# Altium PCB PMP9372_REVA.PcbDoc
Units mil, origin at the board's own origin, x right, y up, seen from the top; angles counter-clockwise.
Board outline 4200 x 2100 mil, 6 copper layers (Top Layer, InternalPlane1, MidLayer2, MidLayer3, InternalPlane2, Bottom Layer), stack 63 mil thick; 93 components, 37 nets, 190 pads, 51 vias.
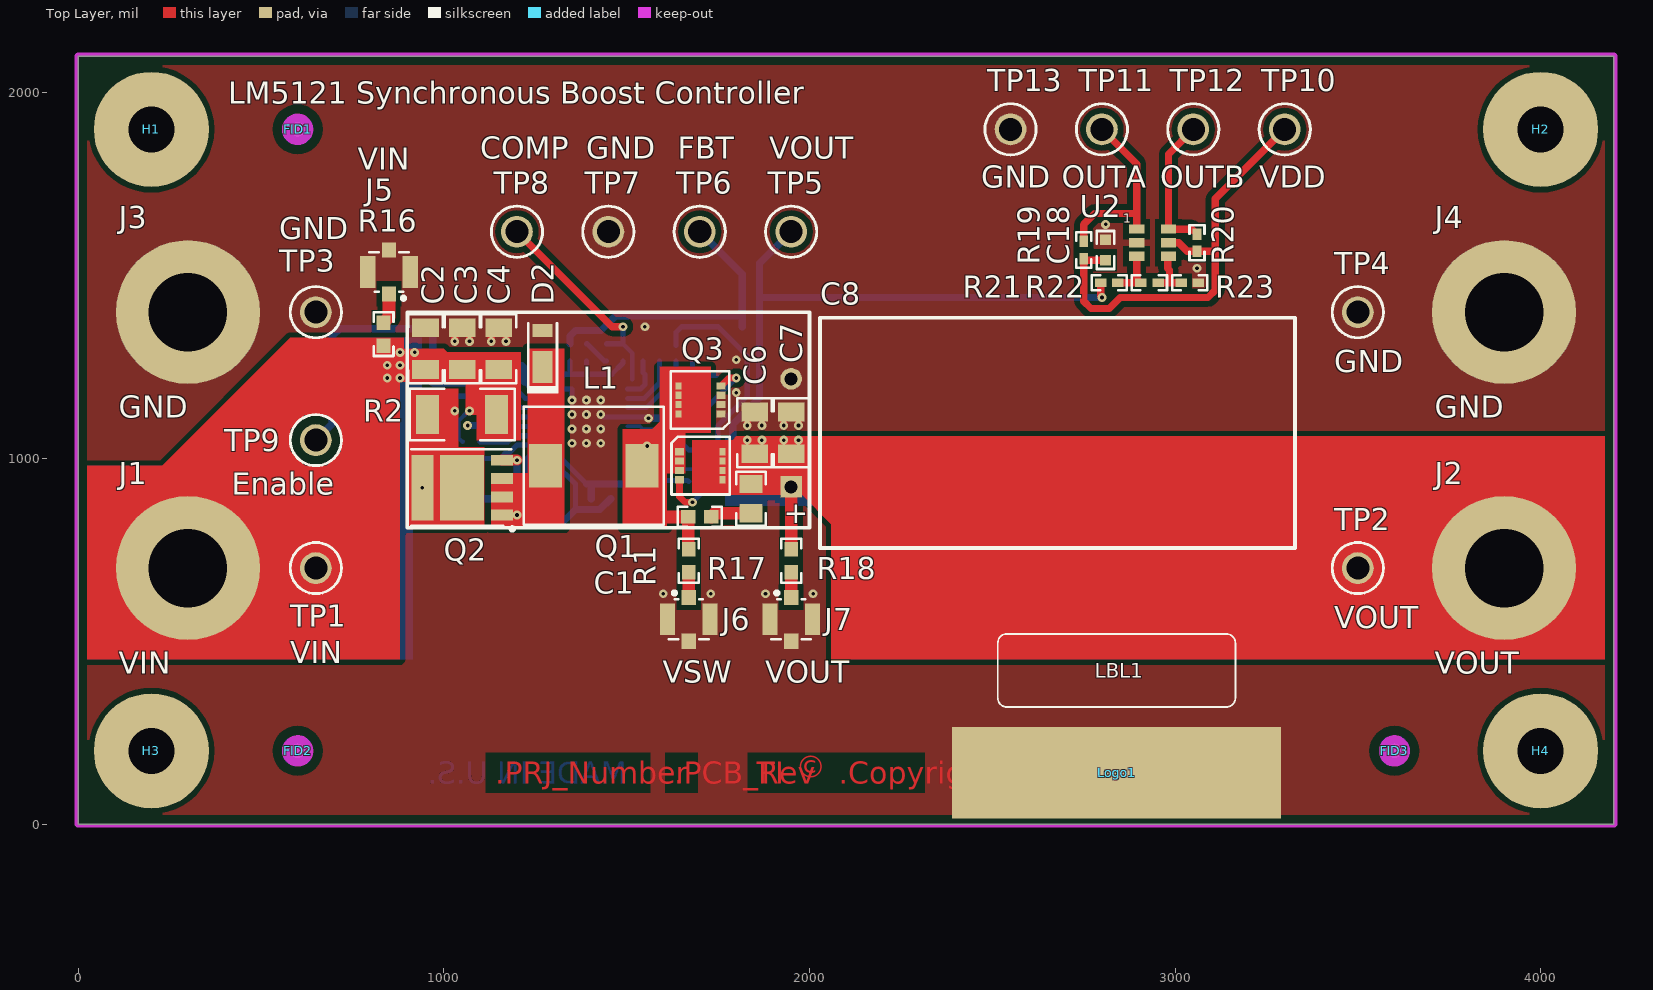
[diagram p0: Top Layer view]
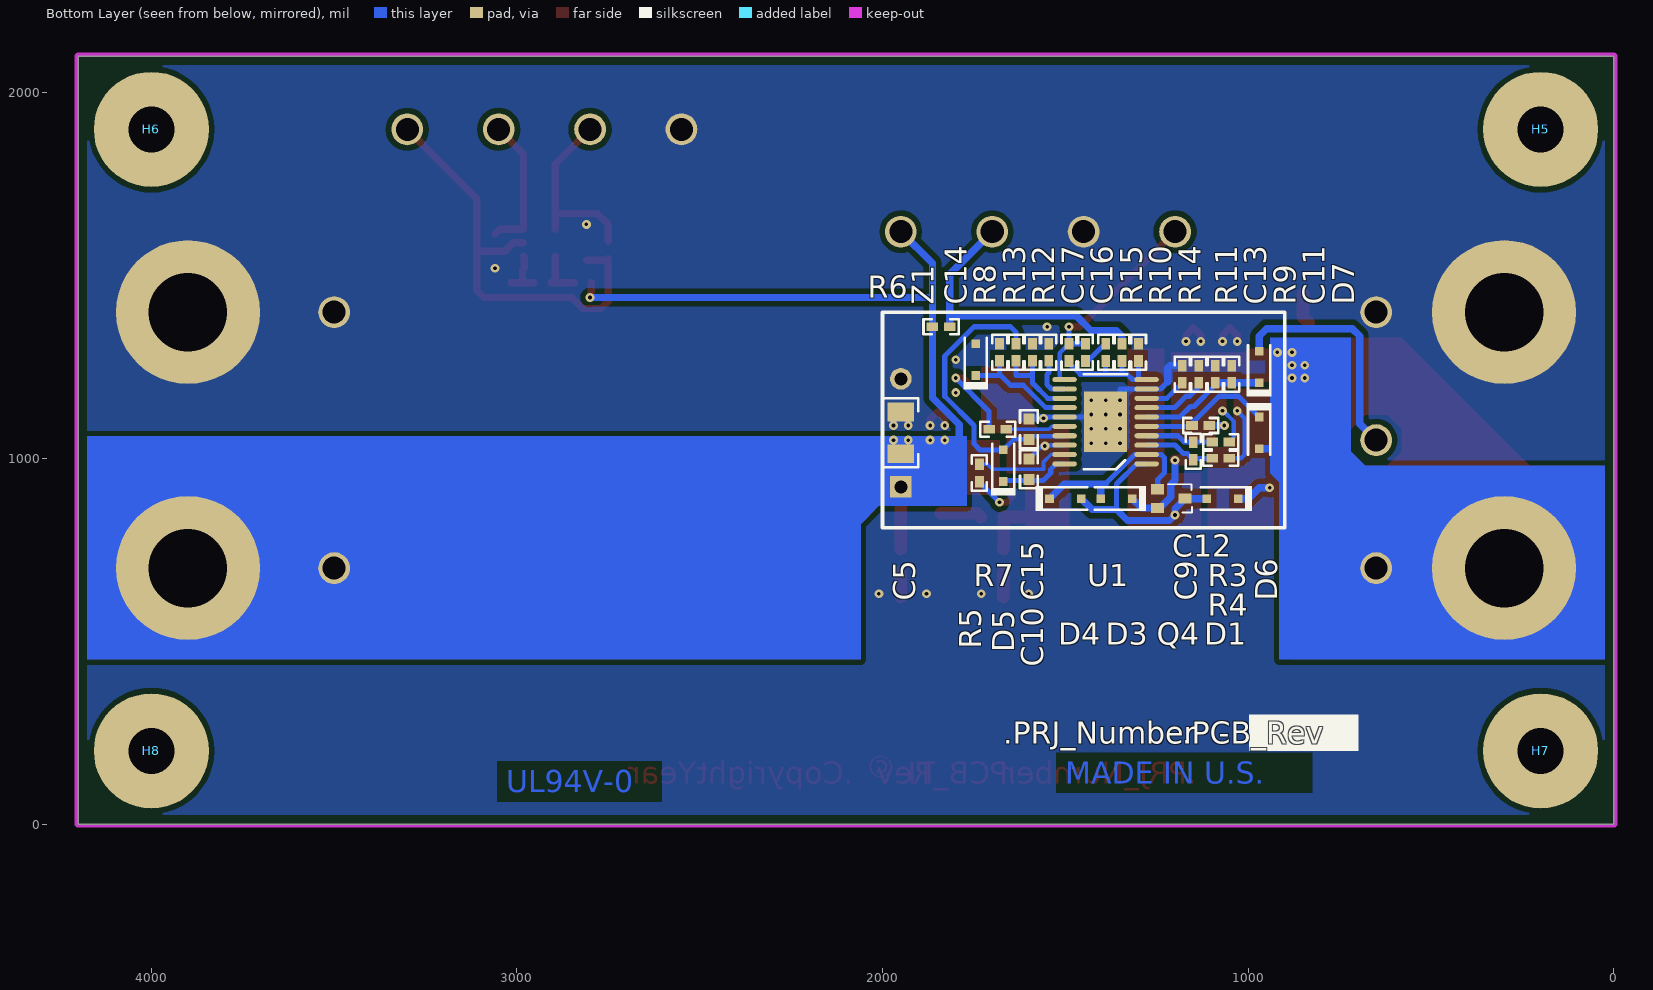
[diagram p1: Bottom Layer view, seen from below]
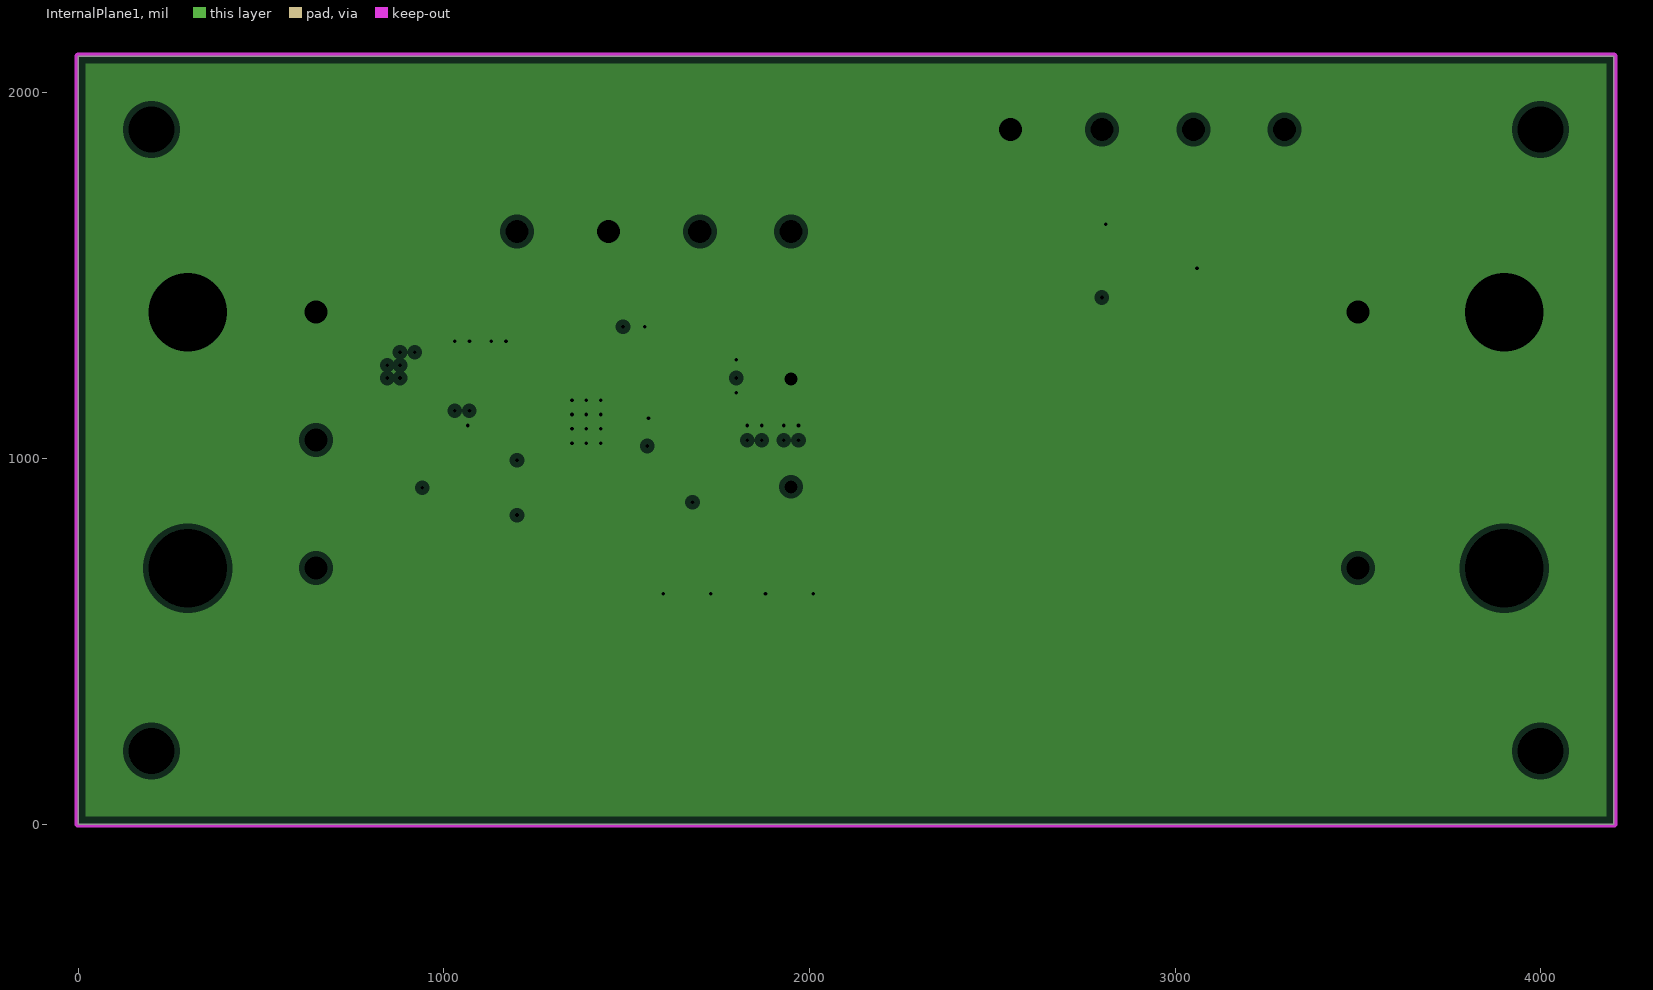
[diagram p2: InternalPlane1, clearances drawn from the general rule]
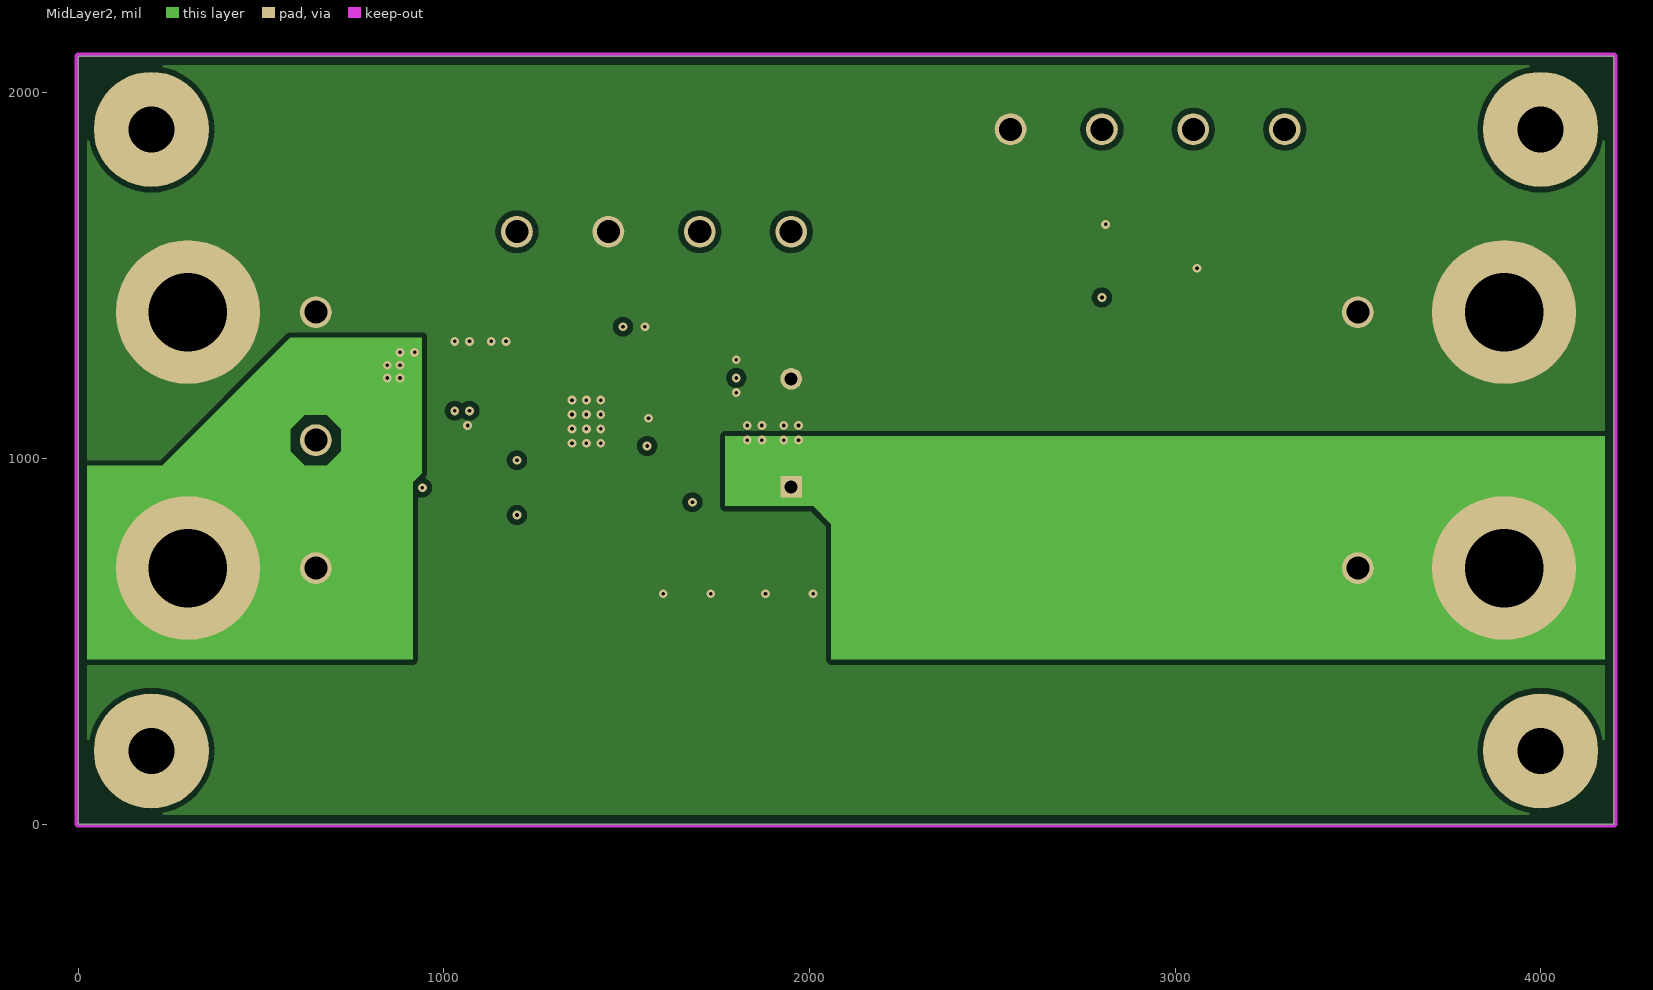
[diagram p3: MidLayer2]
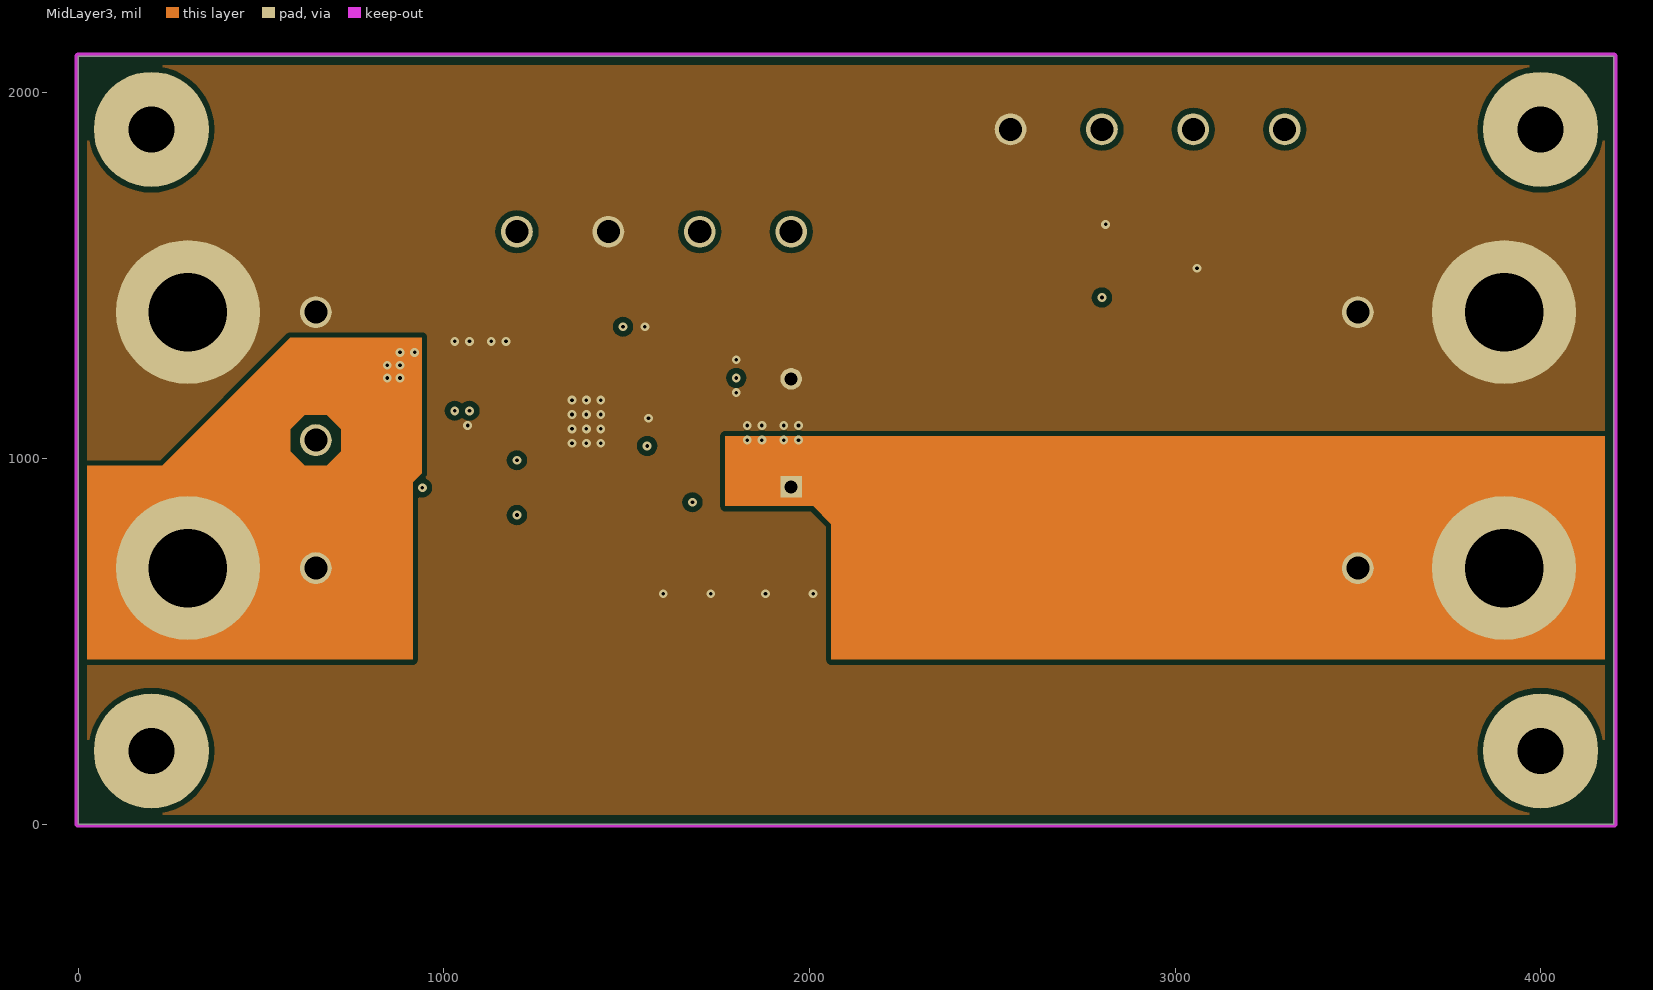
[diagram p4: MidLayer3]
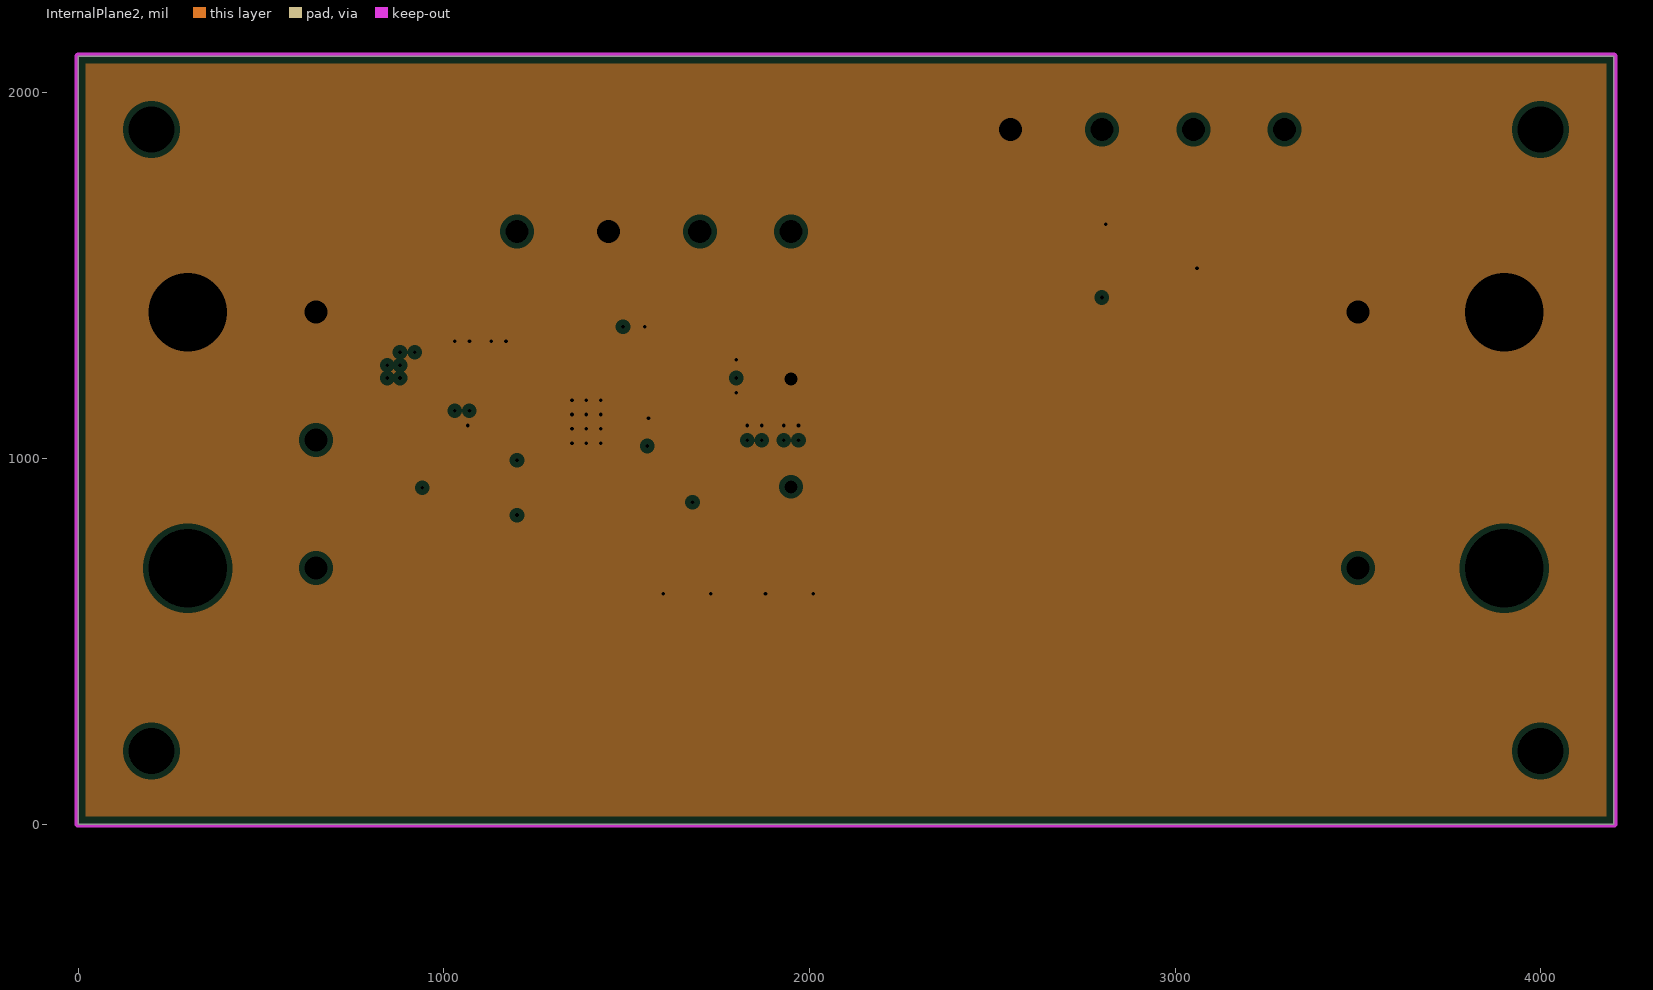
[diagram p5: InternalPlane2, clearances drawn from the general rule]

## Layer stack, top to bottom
Top Layer: signal copper 0.7
Dielectric: core 11.5, FR-4, Dk 4.8
InternalPlane1: plane copper 1.4, net GND
Dielectric: prepreg 11.5, FR-4, Dk 4.8
MidLayer2: signal copper 0.7
Dielectric: core 11.4, FR-4, Dk 4.8
MidLayer3: signal copper 0.7
Dielectric: prepreg 11.5, FR-4, Dk 4.8
InternalPlane2: plane copper 1.4, net GND
Dielectric: core 11.5, FR-4, Dk 4.8
Bottom Layer: signal copper 0.7

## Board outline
0,0 4200,0 4200,2100 0,2100

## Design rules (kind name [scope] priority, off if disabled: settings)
AcuteAngle [All] p1: minimum=4.50000000000000E+0001 checktracksonly=FALSE
AssemblyTestPointUsage [All] p1: valid=2
Clearance Clearance_TRANS_NexFET_Q3 [HasFootprint('TRANS_NexFET_Q3') vs HasFootprint('TRANS_NexFET_Q3')] p1: gap=5.9
Clearance Clearance_BoardEdge_MountingHoles [OnCopper and InComponentClass('Mounting Holes') vs IsKeepOut] p2: gap=40
Clearance Clearance_BoardEdge_Poly [OnCopper and (InPoly or IsCopperRegion or IsTrack or IsFill) vs IsKeepOut] p3: gap=25
Clearance Clearance_BoardEdge [OnCopper and Not InComponentClass('Logo') and not InComponentClass('FiducialMark') and not InRegion(1000,500,4000,800) and Not IsKeepout vs IsKeepOut] p4: gap=75
Clearance Clearance_Poly [InPolygon] p5: gap=15
Clearance [All] p6: gap=8
ComponentClearance ComponentClearance_CAPPR [HasFootprint('CAPPR7.5-16X31.5H*') vs HasFootprint('1206') OR HasFootprint('0805*') OR HasFootprint('0603*')OR HasFootprint('0402*')] p1: gap=0 collisioncheckmode=3 verticalgap=0 showdistances=FALSE
ComponentClearance ComponentClearance_Shunt [InComponentClass('Header') vs InComponentClass('Shunt')] p2: gap=0 collisioncheckmode=3 verticalgap=0 showdistances=FALSE
ComponentClearance ComponentClearance_Logo [InComponentClass('Logo')] p3: gap=50 collisioncheckmode=3 verticalgap=10 showdistances=FALSE
ComponentClearance ComponentClearance_ScrewToNut [(HasFootprint('NY PMS 440 0025 PH')) vs (HasFootprint('Keystone_1902C'))] p4: gap=5 collisioncheckmode=3 verticalgap=10 showdistances=FALSE
ComponentClearance ComponentClearance_MountingHoles [InComponentClass('Mounting Holes')] p5: gap=200 collisioncheckmode=3 verticalgap=100000 showdistances=FALSE
ComponentClearance ComponentClearance_SmallSMT [HasFootprint('0201*') or HasFootprint('0402*') or HasFootprint('0508') or HasFootprint('0603*') or HasFootprint('0612') or HasFootprint('0805*') or HasFootprint('0815*') or HasFootprint('0830*') or HasFootprint('1206*') or HasFootprint('1210*') or HasFootprint('1808*') or HasFootprint('1812*') or HasFootprint('1825*') or HasFootprint('2010*') or HasFootprint('2220*') or HasFootprint('2225*') or HasFootprint('2512*') or HasFootprint('2728*') or HasFootprint('3518*') or HasFootprint('sod-323*') or HasFootprint('sot-323*')or HasFootprint('sot23-6') vs HasFootprint('0201*') or HasFootprint('0402*') or HasFootprint('0508') or HasFootprint('0603*') or HasFootprint('0612') or HasFootprint('0805*') or HasFootprint('0815*') or HasFootprint('0830*') or HasFootprint('1206*') or HasFootprint('1210*') or HasFootprint('1808*') or HasFootprint('1812*') or HasFootprint('1825*') or HasFootprint('2010*') or HasFootprint('2220*') or HasFootprint('2225*') or HasFootprint('2512*') or HasFootprint('2728*') or HasFootprint('3518*') or HasFootprint('sod-323*') or HasFootprint('sot-323*') or HasFootprint('sot23-6')] p6: gap=20 collisioncheckmode=3 verticalgap=10 showdistances=FALSE
ComponentClearance ComponentClearance_THtoSMT [IsThruComponent vs IsSMTComponent] p7: gap=100 collisioncheckmode=3 verticalgap=30 showdistances=FALSE
ComponentClearance ComponentClearance_THtoTH [IsThruComponent vs IsThruComponent] p8: gap=100 collisioncheckmode=3 verticalgap=30 showdistances=FALSE
ComponentClearance [All] p9: gap=40 collisioncheckmode=3 verticalgap=10 showdistances=FALSE
DiffPairsRouting [All] p1: maxlimit=100 minlimit=10 mostfreqgap=10 maxuncoupledlength=1000
FabricationTestPointUsage TestPointUsage [All] p1: valid=2 allowmultiple=FALSE
FabricationTestpoint Testpoint [All] p1: side=3 testpointundercomponent=TRUE minsize=40 maxsize=100 preferedsize=60 minholesize=0 maxholesize=40 preferedholesize=32 testpointgrid=1 allowsidetop=TRUE allowsidebottom=TRUE usegrid=TRUE gridtolerance=0.01
FanoutControl Fanout_LCC [IsLCC] p1: bgadir=Out bgaviamode=Centered fanoutstyle=Auto fanoutdirection=Alternating viagrid=1 // Fanout_LCC (Default Rule)
FanoutControl Fanout_BGA [IsBGA] p2: bgadir=Out bgaviamode=Centered fanoutstyle=Auto fanoutdirection=Alternating viagrid=1 // Fanout_BGA (Default Rule)
FanoutControl Fanout_Default [All] p4: bgadir=Out bgaviamode=Centered fanoutstyle=Auto fanoutdirection=Alternating viagrid=1 // Fanout_Default (Default Rule)
FanoutControl Fanout_Small [(CompPinCount < 5)] p5: bgadir=Out bgaviamode=Centered fanoutstyle=Auto fanoutdirection=OutThenIn viagrid=1 // Fanout_Small (Default Rule)
HoleSize [All] p1: absolutevalues=TRUE maxlimit=251 minlimit=8 maxpercent=80.000 minpercent=20.000
MinimumAnnularRing MinimumAnnularRing_ThermalPadVias [IsVia and InAnyComponent] p1: minimumring=5.91
MinimumAnnularRing [All] p2: minimumring=6
MinimumSolderMaskSliver MinimumSolderMaskSliver_Logo [InComponentClass('Logo') vs InComponentClass('Logo')] p1: minsoldermaskwidth=0.7
MinimumSolderMaskSliver [All] p2: minsoldermaskwidth=3.94
PlaneClearance [All] p1: clearance=15
PlaneConnect [All] p1: planeconnectstyle=Direct reliefexpansion=10 reliefentries=4 reliefconductorwidth=10 reliefairgap=10
PolygonConnect [All] p1: connectstyle=Direct reliefconductorwidth=10 reliefentries=4 polygonreliefangle="90 Angle" airgapwidth=10
RoutingVias ThermalPadVias [IsVia and InAnyComponent] p1: holewidth=10 width=24 viastyle="Through Hole" minholewidth=10 minwidth=24 maxholewidth=10 maxwidth=24
RoutingVias [All] p2: holewidth=16 width=34 viastyle="Through Hole" minholewidth=10 minwidth=24 maxholewidth=40 maxwidth=65
SMDToCorner [All] p1: distance=30000
SilkToSilkClearance [All] p1: silktosilkclearance=5
SilkscreenOverComponentPads [All] p1: minsilkscreentomaskgap=5
SolderMaskExpansion [All] p1: expansion=1.97
Width [All] p1: maxlimit=100 minlimit=10 preferedwidth=10 checkconnectedcopper=TRUE
13 further rules are at their usual default settings.

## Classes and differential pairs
component class "Mounting Holes": H1 H2 H3 H4
component class Logo: Logo1
component class PMP9372_REVA_Sh2: FID1 FID2 FID3 H1 H2 H3 H4 H5 H6 H7 H8 LBL1 Logo1 ZZ1 ZZ2 ZZ3 ZZ4
component class FiducialMark: FID1 FID2 FID3
component class AssemblyNote: ZZ1 ZZ2 ZZ3 ZZ4
component class Label: LBL1

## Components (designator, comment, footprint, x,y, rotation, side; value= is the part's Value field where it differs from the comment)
C1 "GRM1885C1H681JA01D" 0603 1700,840 r180 top
C2 "GRM31CR61E226KE15L" 1206 950,1300 r90 top
C3 "GRM31CR61E226KE15L" 1206 1050,1300 r90 top
C4 "GRM31CR61E226KE15L" 1206 1150,1300 r90 top
C5 "C3216X5R1E476M160AC" 1206 1950,1070 r90 bottom
C6 "C3216X5R1E476M160AC" 1206 1850,1070 r90 top
C7 "C3216X5R1E476M160AC" 1206 1950,1070 r90 top
C8 "UKA1E472MHD" CAPPR7.5-16X31.5H2 1950,1070 r0 top
C9 "GRM1555C1H101JA01D" 0402 1150,1020 r90 bottom
C10 "GRM188R71C104KA01D" 0603_HV 1600,970 r90 bottom
C11 "GRM155R71H103KA88D" 0402 1045,1230.32 r90 bottom
C12 "C1005X5R1E105K050BC" 0402 1130,1090 r180 bottom
C13 "GRM155R61A154KE19D" 0402 1135,1230.32 r90 bottom
C14 "GRM155R71C104KA88D" 0402 1680,1290.32 r90 bottom
C15 "GRM188R61E105KA12D" 0603_HV 1600,1080 r90 bottom
C16 "GRM155R71E103KA01D" 0402 1445,1290 r270 bottom
C17 "C1005C0G1H471J" 0402 1490,1290 r90 bottom
C18 "GRM188R71C104KA01D" 0603_HV 2810,1570 r270 top
D1 "BAT54WS-7-F" sod-323 1070,890 r0 bottom
D2 "DFLS1100-7" powerDI123 1270,1300 r90 top
D3 "BAS316,115" sod-323 1360,890 r0 bottom
D4 "BAS316,115" sod-323 1500,890 r180 bottom
D5 "BAS316,115" sod-323 1670,980 r90 bottom
D6 "BAS316,115" sod-323 970,1070 r270 bottom
D7 "BAS316,115" sod-323 970,1250 r90 bottom
FID1 "Fiducial" Fiducial10-20 600,1900 r0 top
FID2 "Fiducial" Fiducial10-20 600,200 r0 top
FID3 "Fiducial" Fiducial10-20 3600,200 r0 top
H1 "NY PMS 440 0025 PH" "NY PMS 440 0025 PH" 200,1900 r0 top locked
H2 "NY PMS 440 0025 PH" "NY PMS 440 0025 PH" 4000,1900 r0 top locked
H3 "NY PMS 440 0025 PH" "NY PMS 440 0025 PH" 200,200 r0 top locked
H4 "NY PMS 440 0025 PH" "NY PMS 440 0025 PH" 4000,200 r0 top locked
H5 "1902C" Keystone_1902C 200,1900 r180 bottom locked
H6 "1902C" Keystone_1902C 4000,1900 r180 bottom locked
H7 "1902C" Keystone_1902C 200,200 r180 bottom locked
H8 "1902C" Keystone_1902C 4000,200 r180 bottom locked
J1 "VIN" Keystone575-8 300,700 r0 top
J2 "VOUT" Keystone575-8 3900,700 r0 top
J3 "GND" Keystone575-8 300,1400 r0 top
J4 "GND" Keystone575-8 3900,1400 r0 top
J5 "VIN" A-1JB 850,1510 r270 top
J6 "VSW" A-1JB 1670,560 r90 top
J7 "VOUT" A-1JB 1950,560 r90 top
L1 "7443340220" WE-HCC-8X7 1410,980 r0 top
LBL1 "Size: 0.65\" x 0.20 \"" Label_650x200 2840,420 r0 top
Logo1 "Texas Instruments" TI_Stacked_SolderMask_Small 2840,140 r0 top
Q1 "CSD17309Q3" TRANS_NexFET_Q3 1703.35,980 r0 top
Q2 "PSMN1R2-30YLC" LFPAK 1050,920 r90 top
Q3 "CSD17309Q3" TRANS_NexFET_Q3 1700,1160 r180 top
Q4 "2DB1694-7" "SOT-323 DIODES INC" 1210,890 r270 bottom
R1 "CRCW08051R00JNEA" 0805_HV 1840,890 r90 top
R2 "CSRN2010FK10L0" 2010M 1050,1120 r180 top
R3 "CRCW0402100RJNED" 0402 1075,1045 r180 bottom
R4 "CRCW0402100RJNED" 0402 1075,1000 r180 bottom
R5 "CRCW04020000Z0ED" 0402 1735,960 r270 bottom
R6 "CRCW040249R9FKED" 0402 1840,1360 r0 bottom
R7 "CRCW04020000Z0ED" 0402 1685,1080 r0 bottom
R8 "DNP1" 0402 1635,1290.32 r270 bottom
R9 "CRCW0402100KJNED" 0402 1090,1230.32 r270 bottom
R10 "CRCW040223K7FKED" 0402 1345,1290 r90 bottom
R11 "CRCW040220K0FKED" 0402 1180,1230.32 r270 bottom
R12 "CRCW040215K0FKED" 0402 1545,1290.32 r270 bottom
R13 "DNP1" 0402 1590,1290.32 r270 bottom
R14 "CRCW04022K00FKED" 0402 1300,1290 r270 bottom
R15 "CRCW0402100KFKED" 0402 1390,1290 r90 bottom
R16 "CRCW060349R9FKEA" 0603 835,1340 r270 top
R17 "CRCW060349R9FKEA" 0603 1670,720 r90 top
R18 "CRCW060349R9FKEA" 0603 1950,720 r90 top
R19 "CRCW0402100KJNED" 0402 2750,1570 r270 top
R20 "CRCW0402100KJNED" 0402 3060,1590 r270 top
R21 "CRCW0402162KFKED" 0402 2820,1480 r180 top
R22 "CRCW0402604RFKED" 0402 2930,1480 r180 top
R23 "CRCW04024K02FKED" 0402 3040,1480 r180 top
TP1 "VIN" Keystone5010 650,700 r0 top
TP2 "VOUT" Keystone5010 3500,700 r0 top
TP3 "GND" Keystone5011 650,1400 r0 top
TP4 "GND" Keystone5011 3500,1400 r0 top
TP5 "VOUT" Keystone5012 1950,1620 r0 top
TP6 "FBT" Keystone5012 1700,1620 r0 top
TP7 "GND" Keystone5011 1450,1620 r0 top
TP8 "COMP" Keystone5012 1200,1620 r0 top
TP9 "Enable" Keystone5012 650,1050 r0 top
TP10 "VDD" Keystone5010 3300,1900 r0 top
TP11 "OUTA" Keystone5012 2800,1900 r0 top
TP12 "OUTB" Keystone5012 3050,1900 r0 top
TP13 "GND" Keystone5011 2550,1900 r0 top
U1 "LM5121MH/NOPB" PWP0020A_N 1390,1100.32 r0 bottom
U2 "TPS3700DDC" SOT23-6 2940,1590 r0 top
Z1 "CMDZ2L4" sod-323 1745,1270 r90 bottom
ZZ1 "This Assembly Note is for PCB labels only" AssemblyNoteLabel 185,3938 r0 top
ZZ2 "These assemblies are ESD sensitive, ESD precautions shall be observed." AssemblyNote 185,3829.11 r0 top
ZZ3 "These assemblies must be clean and free from flux and all contaminants. Use of no clean flux is not acceptable." AssemblyNote 185,3740.56 r0 top
ZZ4 "These assemblies must comply with workmanship standards IPC-A-610 Class 2, unless otherwise specified." AssemblyNote 185,3652 r0 top

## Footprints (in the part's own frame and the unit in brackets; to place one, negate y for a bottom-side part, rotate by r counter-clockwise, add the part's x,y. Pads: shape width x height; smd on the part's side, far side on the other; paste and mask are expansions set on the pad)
0402 [mm] "0402 from SM-752 data"
  rect 0.8x0.6 smd: 1(-0.6,0) 2(0.6,0)
  silkscreen extent -1.22,-0.52 1.22,0.52, body extent -0.55,-0.3 0.55,0.3, height 0.6
0603 [mm] "0603 from SM-752 data"
  rect 1x0.95 smd: 1(-0.8,0) 2(0.8,0)
  silkscreen extent -1.52,-0.69 1.52,0.69, body extent -0.87,-0.47 0.87,0.47, height 0.85
0603_HV [mil] "Ernesto recommended land pattern.  26 mil between pads."
  rect 30x30 smd: 1(-28,0) 2(28,0)
  silkscreen extent -52,-24 52,24, body extent -34,-19 34,19, height 33
0805_HV [mil] "0805 with 30mil clearance between pads"
  rect 50x63 smd: 1(-40,0) 2(40,0)
  silkscreen extent -74,-40 74,40, body extent -43,-29 43,29, height 43
1206 [mm] "1206 from SM-752 data"
  rect 1.3x1.85 smd: 1(-1.45,0) 2(1.45,0)
  silkscreen extent -2.4,-1.21 2.4,1.21, body extent -1.7,-0.9 1.7,0.9, height 1.35
2010M [mm]
  rect 1.6x2.7 smd: 1(-2.4,0) 2(2.4,0)
  silkscreen extent -3.65,-1.8 3.65,1.8, body extent -2.73,-1.45 2.73,1.45, height 1.66
A-1JB [mm] "Amphenol recommended land pattern"
  rect 1.05x1 smd: 1(1.525,0) 3(-1.525,0)
  rect 2.2x1.05 smd: 2(0,1.475) 4(0,-1.475)
  silkscreen extent -1.38,-1.38 1.95,1.38, body extent -1.38,-1.38 1.38,1.38, height 1.25
AssemblyNote [mil] "Assembly Note"
AssemblyNoteLabel [mil] "Assembly Note for PCB Labels"
CAPPR7.5-16X31.5H2 [mm] "Capacitor, Electrolytic, Radial; Body 16 x 31.5 mm (Dia.xH typ); Pin Spacing 7.5 mm (typ); Horizontal Mount"
  rect 1.5x1.5 hole 0.9: 1(0,-3.75)
  round 1.5 hole 0.9: 2(0,3.75)
  silkscreen extent 2,-8 35,8
Fiducial10-20 [mm]
  round 1 smd paste-0.5 mask+0.5: 1(0,0)
  Top Layer keep-out circle w1.178: c0,0 r0.5
Keystone575-8 [mm] "Banana Jack"
  round 10 hole 5.45: 1(0,0)
  body extent -3.92,-3.94 3.95,3.94, height 2.36
Keystone5010 [mil] "Keystone Multipurpose loops"
  round 87 hole 63: 1(0,0)
  silkscreen extent -70,-70 70,70, body extent -63,-63 63,62, height 319
Keystone5011 [mil] "Keystone Multipurpose loops"
  round 87 hole 63: 1(0,0)
  silkscreen extent -70,-70 70,70, body extent -63,-63 63,62, height 319
Keystone5012 [mil] "Keystone Multipurpose loops"
  round 87 hole 63: 1(0,0)
  silkscreen extent -70,-70 70,70, body extent -63,-63 63,62, height 319
Keystone_1902C [mil] "Hex Standoff, 4-40 threaded, nylon"
  body extent -145,-126 146,126, height 501
Label_650x200 [mil] "Thermal Transfer Label"
  silkscreen extent -325,-100 325,100, body extent -326,-101 326,101, height 1
LFPAK [mm] "Renesas LFPAK recommended land pattern  2008-05-26, page 17 of REJ11K0001_surface.pdf"
  rect 0.76x1.52 smd: 1(-1.905,-2.76) 2(-0.635,-2.76) 3(0.635,-2.76) 4(1.905,-2.76)
  rect 4.57x3.04 smd paste-1.52: 5(0,0)
  rect 4.57x1.52 smd paste-0.76: 6(0,2.76)
  silkscreen extent -2.99,-3.61 2.66,3.52, body extent -2.45,-3.23 2.45,3.2, height 1.18
"NY PMS 440 0025 PH" [mm] "4-40 nylon screw and mounting hole"
  round 8 hole 3.2: 1(0,0)
  body extent -3.3,-3.3 3.3,3.3, height 2.69
powerDI123 [mm] "Diodes Inc recommended land pattern, document number DS30628 Rev. 6-2"
  rect 2.2x1.4 smd: 1(-1.275,0)
  rect 0.9x1.4 smd: 2(1.275,0)
  silkscreen extent -3.1,-1.09 1.76,1.09, body extent -2.38,-0.97 1.52,0.96, height 1
PWP0020A_N [mm] "TSOP, 20-Leads, Body 6.5x4.4mm, Pitch 0.65mm, Exposed Pad, IPC Medium Density"
  oval 1.7x0.35 smd: 1(-2.85,2.925) 2(-2.85,2.275) 3(-2.85,1.625) 4(-2.85,0.975) 5(-2.85,0.325) 6(-2.85,-0.325) 7(-2.85,-0.975) 8(-2.85,-1.625) 9(-2.85,-2.275) 10(-2.85,-2.925) 11(2.85,-2.925) 12(2.85,-2.275) 13(2.85,-1.625) 14(2.85,-0.975) 15(2.85,-0.325) 16(2.85,0.325) 17(2.85,0.975) 18(2.85,1.625) 19(2.85,2.275) 20(2.85,2.925)
  rect 3x4.2 smd: 21(0,0)
  silkscreen extent -1.5,-3.3 1.5,3.3, body extent -3.21,-3.25 3.21,3.25, height 0.98
sod-323 [mm] "NXP recommended land pattern"
  rect 0.6x0.6 smd paste-0.05: 1(-1.1,0) 2(1.1,0)
  silkscreen extent -2.06,-0.86 1.53,0.86, body extent -1.3,-0.67 1.3,0.68, height 1.1
SOT23-6 [mil]
  rect 42x25 smd: 1(-45,37) 2(-45,0) 3(-45,-37) 4(42,-37) 5(42,0) 6(42,37)
"SOT-323 DIODES INC" [mm] "SOT-323 DIODES INC"
  round 0.25 on Bottom Overlay: 0(-1.3,-0.95)
  rect 0.7x0.9 smd: 1(-0.65,-0.95) 2(0.65,-0.95) 3(0,0.95)
  silkscreen extent -1,-0.25 0.97,1.43, body extent -1,-1.45 0.97,1.5, height 1
TI_Stacked_SolderMask_Small [mil]
  rect 900x250 smd paste-125 mask-125: 0(0,0)
TRANS_NexFET_Q3 [mm] "TI recommended land pattern (nominal) M0143-01"
  rect 0.63x0.5 smd mask+0.076: 1(-1.49,0.975) 2(-1.49,0.325) 3(-1.49,-0.325) 4(-1.49,-0.975)
  rect 0.41x0.5 smd mask+0.076: 5(1.49,-0.975) 6(1.49,-0.325) 7(1.49,0.325) 8(1.49,0.975)
  Top Layer region: -0.615,-1.225 1.285,-1.225 1.285,1.225 -0.615,1.225
  silkscreen extent -2.05,-2 2,2, body extent -1.76,-1.7 1.66,1.7, height 1.11
WE-HCC-8X7 [mm] "Wurth Elektronik recommended land pattern"
  rect 2.3x3 smd: 1(-3.35,0) 2(3.35,0)
  silkscreen extent -4.85,-4.1 4.85,4.1, body extent -4.4,-4.1 4.4,4.1, height 7.5

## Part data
C1: "CAP, CERM, 680pF, 50V, +/-5%, C0G/NP0, 0603"
C2 C3 C4: "CAP, CERM, 22uF, 25V, +/-10%, X5R, 1206"
C5 C6 C7: "CAP, CERM, 47uF, 25V, +/-20%, X5R, 1206"
C8: "CAP, AL, 4700uF, 25V, +/-20%, TH"
C9: "CAP, CERM, 100pF, 50V, +/-5%, C0G/NP0, 0402"
C10 C18: "CAP, CERM, 0.1uF, 16V, +/-10%, X7R, 0603"
C11: "CAP, CERM, 0.01uF, 50V, +/-10%, X7R, 0402"
C12: "CAP, CERM, 1uF, 25V, +/-10%, X5R, 0402"
C13: "CAP, CERM, 0.15uF, 10V, +/-10%, X5R, 0402"
C14: "CAP, CERM, 0.1uF, 16V, +/-10%, X7R, 0402"
C15: "CAP, CERM, 1uF, 25V, +/-10%, X5R, 0603"
C16: "CAP, CERM, 0.01uF, 25V, +/-10%, X7R, 0402"
C17: "CAP, CERM, 470pF, 50V, +/-5%, C0G/NP0, 0402"
D1: "Diode, Schottky, 30V, 0.2A, SOD-323"
D2: "Diode, Schottky, 100V, 1A, PowerDI123"
D3 D4 D5 D6 D7: "Diode, Ultrafast, 100V, 0.25A, SOD-323"
FID1 FID2 FID3: "Fiducial mark.  There is nothing to buy or mount."
H1 H2 H3 H4: "Machine Screw, Round, #4-40 x 1/4, Nylon, Philips panhead"
H5 H6 H7 H8: "Standoff, Hex, 0.5\"L #4-40 Nylon"
J1 J2 J3 J4: library part 575-8, "Standard Banana Jack, Uninsulated, 8.9mm"
J5 J6 J7: library part A-1JB, "Connector, RF Jack, Vertical, Gold, SMD"
L1: "Inductor, Shielded Drum Core, Ferrite, 2.2uH, 12.5A, 0.0044 ohm, SMD"
LBL1: library part THT-14-423-10, "Thermal Transfer Printable Labels, 0.650\" W x 0.200\" H - 10,000 per roll"
Logo1: library part TI_Logo, "Texas Instrument Corporate Signature"
Q1 Q3: "MOSFET, N-CH, 30V, 60A, SON 3.3x3.3mm"
Q2: "MOSFET, N-CH, 30V, 100A, LFPAK"
Q4: "TRANS BIPO PNP 30V 1A SOT-323"
R1: "RES, 1.0 ohm, 5%, 0.125W, 0805"
R2: "RES, 0.01 ohm, 1%, 1W, 2010"
R3 R4: "RES, 100 ohm, 5%, 0.063W, 0402"
R5 R7: "RES, 0 ohm, 5%, 0.063W, 0402"
R6: "RES, 49.9 ohm, 1%, 0.063W, 0402"
R8 R13: library part Resistor, "RES, xxx ohm, x%, xW, [PackageReference]"
R9 R19 R20: "RES, 100k ohm, 5%, 0.063W, 0402"
R10: "RES, 23.7k ohm, 1%, 0.063W, 0402"
R11: "RES, 20.0k ohm, 1%, 0.063W, 0402"
R12: "RES, 15.0k ohm, 1%, 0.063W, 0402"
R14: "RES, 2.00k ohm, 1%, 0.063W, 0402"
R15: "RES, 100k ohm, 1%, 0.063W, 0402"
R16 R17 R18: "RES, 49.9 ohm, 1%, 0.1W, 0603"
R21: "RES, 162k ohm, 1%, 0.063W, 0402"
R22: "RES, 604 ohm, 1%, 0.063W, 0402"
R23: "RES, 4.02k ohm, 1%, 0.063W, 0402"
TP1 TP2 TP10: library part 5010, "Test Point, Multipurpose, Red, TH"
TP3 TP4 TP7 TP13: library part 5011, "Test Point, Multipurpose, Black, TH"
TP5 TP6 TP8 TP9 TP11 TP12: library part 5012, "Test Point, Multipurpose, White, TH"
U1: "Wide Input Synchronous Boost Controller with Disconnection Switch Control, PWP0020A"
U2: "IC,  High Voltage, Over-Under Voltage Supervisory"
Z1: library part MMSZ5242BS-7-F, "Diode, Zener, 2.4V, Sharp Knee, SOD-323"
ZZ1: library part AssemblyNoteLabel
ZZ2 ZZ3 ZZ4: library part AssemblyNote

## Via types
v1: diameter 24, hole 10, Top Layer to Bottom Layer, 38 vias
v2: diameter 24, hole 10, Top Layer to Bottom Layer, tented top, 13 vias

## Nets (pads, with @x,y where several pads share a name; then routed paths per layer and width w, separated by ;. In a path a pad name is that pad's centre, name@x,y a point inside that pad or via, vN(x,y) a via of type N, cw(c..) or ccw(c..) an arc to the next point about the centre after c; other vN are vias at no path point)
BST: C10.1 D5.1 U1.20 | length 193.7
  Bottom Layer w14: U1.20 1524.84,985.16 1540,970 1540,960 1560,940 1666.69,940 D5.1
CMP: C16.2 R15.2 | length 74.6
  Bottom Layer w14: R15.2 1391.53,1313.62 1438.77,1266.38 C16.2
COMP: C16.1 C17.2 TP8.1 U1.11 | length 597.5
  Top Layer w20: TP8.1 1460,1360 v1(1490,1360)
  Bottom Layer w12: C17.2 1490.11,1313.62 1515.81,1287.93 U1.11@1515.81,1216
  Bottom Layer w14: C16.1 C17.2 v1(1490,1360)
CSN: C9.1 R4.1 U1.3 | length 197.2
  Bottom Layer w14: R4.1 1146.38,1000 C9.1 1166.5,1012.87 1176.81,1012.87 1200.28,1036.34 U1.3
CSP: C9.2 R3.1 U1.4 | length 186.2
  Bottom Layer w14: R3.1 1175,1045 1191.93,1061.93 U1.4
DG: D3.2 D4.1 Q4.1 U1.2 | length 501.7
  Bottom Layer w14: Q4.1 1247.4,941.93 1229.33,960 1229.33,1002.33 1237.75,1010.75 U1.2 1310.36,1010.75 1391.11,930
  Bottom Layer w20: 1391.11,930 1403.31,930 ; D3.2 1403.31,930 ; D4.1 1503.31,930 1403.31,930
DS: D1.2 D2.1 D4.2 L1.1 Q2.1 Q2.2 Q2.3 Q4.3 U1.1 | length 578.5
  Bottom Layer w14: U1.1 1304.84,985.16 1360,930 1360,860
  Bottom Layer w20: D1.2 Q4.3 1200,862.6 v1(1200,845) 1215,830 1330,830 1360,860 1426.69,860 D4.2
EN: D7.2 TP9.1 | length 636.9
  Bottom Layer w20: TP9.1 695,1095 695,1335 715,1355 950,1355 970,1335 D7.2
FB: C17.1 R10.1 R14.2 R15.1 U1.10 | length 361.8
  Bottom Layer w14: U1.10 U1.10@1300,1215.47 ; R14.2 U1.10@1300,1215.47 ; R10.1 1345,1235.24 1340,1230.24 ; R15.1 1390,1230.24 ; C17.1 1490,1260.8 1459.44,1230.24 1390,1230.24 ; U1.10@1300,1215.47 1316.18,1215.47 1330.94,1230.24 1340,1230.24 ; 1340,1230.24 1390,1230.24
FBT: R6.1 R10.2 TP6.1 | length 823.7
  Bottom Layer w20: R10.2 1345,1335 1360,1350 1430,1350 1470,1390 1816.38,1390 ; TP6.1 1816.38,1503.62 R6.1
GND: C2.2 C3.2 C4.2 C5.2 C6.2 C7.2 C8.2 C11.2 C12.2 C13.2 C14.2 C15.2 C18.1 D2.2 J3.1 J4.1 J5.2 J5.3 J5.4 J6.2 J6.3 J6.4 J7.2 J7.3 J7.4 Logo1.0 Q3.1 Q3.2 Q3.3 R9.1 R11.1 R12.1 R13.1 R14.1 R23.1 TP3.1 TP4.1 TP7.1 TP13.1 U1.9 U1.15 U1.21 U2.2 Z1.2 | length 921.5
  Top Layer w20: v1(1030,1320) 1030,1337.09 C3.2 1070,1337.09 v1(1070,1320) ; v1(1130,1320) 1130,1337.09 C4.2 1170,1337.09 v1(1170,1320) ; v1(1830,1090) 1830,1107.09 C6.2 1870,1107.09 v1(1870,1090) ; v1(1930,1090) 1930,1107.09 C7.2 1970,1107.09 v1(1970,1090)
  Bottom Layer w14: 1220,1210 1240.12,1189.88 U1.9 1349.88,1189.88 1350,1190 1350.63,1189.37 v2(1350.63,1159.37) ; v2(1429.37,1120) 1436.26,1113.11 U1.15 1556.89,1113.11 v2(1560,1110)
  Bottom Layer w20: v1@1064,1091 v1(1065,1090) C12.2 ; R11.1 1213.5,1253.94 1220,1247.44 1220,1210 ; v2(1560,1110) 1598,1110 C15.2 ; v1(1930,1090) 1930,1107.09 C5.2 1970,1107.09 v1(1970,1090)
  other v1: 1600,630 1730,630 1880,630 2010,630 1800,1180 1800,1270 1550,1360 3060,1520 2810,1640
  other v2: 1350.63,1041.26 1390,1041.26 1429.37,1041.26 1350.63,1080.63 1390,1080.63 1429.37,1080.63 1350.63,1120 1390,1120 1390,1159.37 1429.37,1159.37
HG: Q1.4 R5.2 | length 160.5
  Top Layer w18: Q1.4@1644.69,935 1644.69,895.31 1660,880 v1(1680,880)
  Bottom Layer w14: v1(1680,880) 1735,935 R5.2
HO: R5.1 U1.19 | length 266.5
  Bottom Layer w10: U1.19@1502.83,1011.06 1538.94,1011.06 1560,990 1560,970 1700,970 1713.62,983.62 R5.1
INA: R21.1 R22.2 U2.3 | length 140.5
  Top Layer w20: R21.1 R22.2 2895,1491.38 U2.3
INB: R22.1 R23.2 U2.4 | length 138.7
  Top Layer w20: R22.1 2985,1480 ; U2.4 2980,1551 2980,1520 2985,1515 2985,1480 ; R23.2 2985,1480
LG: Q3.4 R7.2 | length 223.2
  Top Layer w18: Q3.4@1762.14,1201.86 1780.28,1220 v1(1800,1220)
  Bottom Layer w14: R7.2 1708.62,1128.62 v1(1800,1220)
LO: R7.1 U1.16 | length 162.3
  Bottom Layer w10: U1.16 1537.48,1087.52 1545,1080 R7.1
MODE: R8.2 R13.2 U1.13 | length 250.4
  Bottom Layer w14: U1.13 1548.18,1164.29 1590,1206.11 1590,1227 ; R13.2 1590,1227 ; R8.2 1635,1227 1590,1227
OUTA: R19.1 TP11.1 U2.1 | length 516.2
  Top Layer w20: R19.1 2750,1640 2780,1670 2895,1670 ; TP11.1 2895,1805 2895,1670 ; U2.1 2895,1670
OUTB: R20.1 TP12.1 U2.6 | length 384.7
  Top Layer w20: TP12.1 2982,1832 U2.6 3046.62,1627 R20.1
RES: C14.1 U1.14 Z1.1 | length 320.6
  Bottom Layer w14: U1.14 1553.7,1138.7 1615,1200 1650,1200 1676.69,1226.69 ; C14.1 1680,1230 1676.69,1226.69 ; Z1.1 1676.69,1226.69
RT: R11.2 U1.8 | length 115.4
  Bottom Layer w14: R11.2 1222.4,1164.29 U1.8
SLOPE: R12.2 U1.12 | length 120.3
  Bottom Layer w14: U1.12 1538.13,1189.88 1550.67,1202.42 1550.67,1229.33 1545,1235 R12.2
SNB: C1.1 R1.1 | length 112.6
  Top Layer w35: C1.1 1741.5,850 R1.1
SS: C13.1 U1.7 | length 177.8
  Bottom Layer w14: C13.1 1135,1195 1160,1170 1170,1170 1201.3,1138.7 U1.7
SW: C1.2 C10.2 L1.2 Q1.1 Q1.2 Q1.3 Q3.5 Q3.6 Q3.7 Q3.8 R17.2 U1.18 | length 321.3
  Top Layer w35: 1550,840 C1.2 1668.5,752.99 R17.2
  Bottom Layer w12: U1.18 1561.66,1036.34 C10.2
  other v1: 1556,1034
UVLO: C11.1 D7.1 R9.2 U1.6 | length 352.5
  Bottom Layer w14: R9.2 1090,1200 1148,1142 ; 1150,1142 1148,1142 ; U1.6 1186.89,1113.11 1158,1142 1148,1142
  Bottom Layer w20: D7.1 C11.1 R9.2
VCC: C15.1 D5.2 R8.1 U1.17 | length 814.6
  Bottom Layer w10: C15.1@1599.73,1051.73 C15.1
  Bottom Layer w12: U1.17 1503.13,1061 1591,1061 C15.1 1641.31,1052 D5.2
  Bottom Layer w14: R8.1@1635,1308.94 1635,1345 1650,1360 1750,1360 1830,1280 1830,1170 1750,1090 1750,1040 1733.31,1023.31 D5.2
VDD: C18.2 R19.2 R20.2 TP10.1 U2.5 | length 1228.8
  Top Layer w20: C18.2 2754.38,1542 R19.2 2750,1430 2770,1410 2820,1410 2850,1440 3090,1440 3110,1460 3110,1570 ; U2.5 3010,1590 3033.62,1566.38 3110,1566.38 ; 3106.38,1566.38 3110,1570 ; TP10.1 3110,1710 3110,1570
VG: D3.1 Q2.4 Q4.2 | length 274.8
  Top Layer w30: Q2.4 v1(1200,995)
  Bottom Layer w20: v1(1200,995) 1200,940 1211.68,928.32 1211.68,894.36 1241.63,864.41 Q4.2 1291.1,864.41 D3.1
VI: J5.1 R16.1 | length 84.7
  Top Layer w35: R16.1 850,1386.5 J5.1
VIN: C2.1 C3.1 C4.1 D6.2 J1.1 R2.1 R3.2 R16.2 TP1.1 | length 417.3
  Bottom Layer w12: R3.2 1039,1057.38 1039,1100.77 1068.23,1130 v1(1070,1130)
  Bottom Layer w20: v1(920,1290) 920,1026.69 D6.2
  other v1: 845,1220 880,1220 845,1255 880,1255 880,1290
VINP: C12.1 D6.1 U1.5 | length 371
  Bottom Layer w14: D6.1 1026.69,1170 1080,1170 C12.1@1159.36,1090.64 ; C12.1@1153.62,1090.13 1156.24,1087.52 U1.5
VO: J7.1 R18.1 | length 68.5
  Top Layer w35: J7.1 R18.1
VOUT: C5.1 C6.1 C7.1 C8.1 J2.1 Q1.5 Q1.6 Q1.7 Q1.8 R1.2 R6.2 R18.2 R21.2 TP2.1 TP5.1 | length 1977.7
  Top Layer w20: R21.2 2796.38,1443.62 v1(2800,1440)
  Top Layer w35: R18.2 C8.1
  Bottom Layer w20: C5.1@1942.91,1020 C5.1 1814.59,1012.91 1790,1037.5 1790,1092.64 1863.62,1166.26 R6.2 1863.62,1440 ; TP5.1 1863.62,1533.62 1863.62,1440 ; v1(2800,1440) 1863.62,1440
  other v1: 1830,1050 1870,1050 1930,1050 1970,1050
VR: D1.1 Q2.5 Q2.6 R2.2 R4.2 | length 271.6
  Bottom Layer w12: v1(1030,1130) 1010,1110 1010,1010 1020,1000 R4.2
  Bottom Layer w20: v1(941.34,920) 970,920 1000,890 D1.1
VS: J6.1 R17.1 | length 68.5
  Top Layer w35: J6.1 R17.1
pads on no net: FID1.1 FID2.1 FID3.1 H1.1 H2.1 H3.1 H4.1 Q4.0

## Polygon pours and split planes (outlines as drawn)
GND on MidLayer3 "MidLayer3-GND" (solid, remove dead copper, pour order 7): 0,0 0,2100 4200,2100 4200,0 0,0
GND on MidLayer2 "MidLayer2-GND" (solid, remove dead copper, pour order 6): 0,0 0,2100 4200,2100 4200,0 0,0
GND on Top Layer "Top Layer-GND" (solid, remove dead copper, pour order 5): 0,0 0,2100 4200,2100 4200,0 0,0
GND on Bottom Layer "Bottom Layer-GND" (solid, remove dead copper, pour order 8): 0,0 0,2100 4200,2100 4200,0 0,0
GND on InternalPlane1 (split plane): 4179.9,20.1 20.1,20.1 20.1,2079.9 4179.9,2079.9
GND on InternalPlane2 (split plane): 4179.9,20.1 20.1,20.1 20.1,2079.9 4179.9,2079.9

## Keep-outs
Keep-Out Layer:
  lines w10: -5,0 ccw(c0,0) 0,-5 ; -5,0 ccw(c0,0) 0,-5 ; -5,0 ccw(c0,0) 0,-5 ; -5,0 ccw(c0,0) 0,-5 ; -5,0 ccw(c0,0) 0,-5 ; -5,0 ccw(c0,0) 0,-5 ; -5,0 -5,2100 ; -5,2100 cw(c0,2100) 0,2105 ; -5,2100 cw(c0,2100) 0,2105 ; -5,2100 cw(c0,2100) 0,2105 ; -5,2100 cw(c0,2100) 0,2105 ; -5,2100 cw(c0,2100) 0,2105 ; -5,2100 cw(c0,2100) 0,2105 ; 0,-5 4200,-5 ; 0,2105 4200,2105 ; 4200,-5 ccw(c4200,0) 4205,0 ; 4200,-5 ccw(c4200,0) 4205,0 ; 4200,-5 ccw(c4200,0) 4205,0 ; 4200,-5 ccw(c4200,0) 4205,0 ; 4200,-5 ccw(c4200,0) 4205,0 ; 4200,-5 ccw(c4200,0) 4205,0 ; 4200,2105 cw(c4200,2100) 4205,2100 ; 4200,2105 cw(c4200,2100) 4205,2100 ; 4200,2105 cw(c4200,2100) 4205,2100 ; 4200,2105 cw(c4200,2100) 4205,2100 ; 4200,2105 cw(c4200,2100) 4205,2100 ; 4200,2105 cw(c4200,2100) 4205,2100 ; 4205,0 4205,2100
  text ".Layer_Name" at 577,-858.49 h60

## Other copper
Top Layer:
  region net VIN: 25,980 680,980 720,1020 720,1330 890,1330 890,1300 1000,1300 1010,1290 1210,1290 1210,1050 1090,1050 1090,1120 1060,1120 1060,1205.51 1055.51,1210 880,1210 880,450 25,450
  region net VR: 900,810 900,1190 1040,1190 1040,1030 1110,1030 1110,810
  region net DS: 1130,810 1130,960 1230,960 1230,1300 1330,1300 1330,810
  region net SW: 1490,810 1490,1080 1570,1080 1590,1100 1590,1250 1730,1250 1730,1070 1660,1070 1660,960 1610,960 1610,810
  region net VOUT: 1680,1050 1790,1050 1800,1060 4175,1060 4175,450 2060,450 2060,820 1980,900 1710,900 1680,901.89
  region net VIN: 230,980 580,1330 720,1330 720,1080 680,1120 620,1120 580,1080 580,1020 620,980
  text ".PRJ_Number" at 1140,110 h60
  text ".PCB_Rev" at 1630,110 h60
  text "TI" at 1856,110 h60
  text ".CopyrightYear" at 2080,110 h60
  text "©" at 1963,106.48 h105
  text ".Layer_Name" at 577,-858.49 h60
MidLayer2:
  region net VIN: 25,980 680,980 720,1020 720,1330 940,1330 940,960 915,935 915,450 25,450
  region net VIN: 230,980 580,1330 720,1330 720,1080 680,1120 620,1120 580,1080 580,1020 620,980
  region net VOUT: 1770.26,1060 4175,1060 4175,450 2060.26,450 2060.26,820 2010.26,870 1770.26,870
  text ".Layer_Name" at 577,-858.49 h60
MidLayer3:
  region net VIN: 25,980 680,980 720,1020 720,1330 940,1330 940,960 915,935 915,450 25,450
  region net VIN: 230,980 580,1330 720,1330 720,1080 680,1120 620,1120 580,1080 580,1020 620,980
  region net VOUT: 1770,1060 4175,1060 4175,450 2060,450 2060,820 2010,870 1770,870
  text ".Layer_Name" at 577,-858.49 h60
Bottom Layer:
  rectangle net VOUT: 1770,870 2010,1060
  region net VIN: 25,980 680,980 720,1020 720,1330 940,1330 940,960 915,935 915,450 25,450
  region net VOUT: 1770,1060 4175,1060 4175,450 2060,450 2060,820 2010,870 1770,870
  text ".VersionControl_RevNumber" at 3921,2230 h60
  text "SVN:" at 4200,2230 h60
  text "MADE IN U.S." at 1500,110 h60
  text "UL94V-0" at 3029.5,86.5 h60
  text ".Layer_Name" at 577,-858.49 h60
InternalPlane1 (plane layer: these items are gaps in the copper):
  text ".Layer_Name" at 577,-858.49 h60
InternalPlane2 (plane layer: these items are gaps in the copper):
  text ".Layer_Name" at 577,-858.49 h60

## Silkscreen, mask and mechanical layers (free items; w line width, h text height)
Top Overlay:
  lines w10: 900,810 2000,810 2000,1400 900,1400 900,810
  text "LM5121 Synchronous Boost Controller" at 410,1970 h60
  text ".Layer_Name" at 577,-858.49 h60
Bottom Overlay:
  rectangle: 698,200 998,300
  lines w10: 900,810 900,1400 2000,1400 2000,810 900,810
  text "-" at 1080,220 h60
  text ".PCB_Rev" at 1180,220 h60
  text ".PRJ_Number" at 1670,220 h60
  text ".Layer_Name" at 577,-858.49 h60
Top Paste:
  text ".Layer_Name" at 577,-858.49 h60
Bottom Paste:
  text ".Layer_Name" at 577,-858.49 h60
Top Solder:
  text ".Layer_Name" at 577,-858.49 h60
  text ".Layer_Name" at 577,-858.49 h60
Bottom Solder:
  text ".Layer_Name" at 577,-858.49 h60
Drill Guide:
  text ".Layer_Name" at 577,-858.49 h60
M1 Board Outline:
  the board outline again, w10
  text ".Layer_Name" at 577,-858.49 h60
M2 Board Dimensions:
  rectangle: -0.5,-285.5 124.5,-160.5
  rectangle: 124.5,-410.5 499.5,-285.5
  lines w7: -0.5,-285.5 999.5,-285.5 ; 124.5,-410.5 124.5,-160.5 ; 249.5,-410.5 249.5,-160.5 ; 499.5,-410.5 499.5,-160.5 ; 749.5,-410.5 749.5,-160.5 ; -0.5,-410.5 999.5,-410.5 999.5,-160.5 -0.5,-160.5 -0.5,-410.5
  lines w10: -0.5,-475.5 -0.5,-455.5 ; 59.5,-485.5 -0.5,-465.5 ; 59.5,-445.5 -0.5,-465.5 ; 223.58,-465.5 -0.5,-465.5 ; 775.42,-465.5 999.5,-465.5 ; 939.5,-485.5 999.5,-465.5 ; 939.5,-445.5 999.5,-465.5 ; 999.5,-475.5 999.5,-455.5
  text "1000 (mil)" at 233.58,-501.49 h60
  text ".Layer_Name" at 577,-858.49 h60
M3 3D STEP Top:
  text ".Layer_Name" at 577,-858.49 h60
M4 3D STEP Bottom:
  text ".Layer_Name" at 577,-858.49 h60
M5 Assembly Top:
  lines w10: -292,-930.17 6308,-930.17 ; -292,-726.83 6310,-726.83 ; -292,-523.5 -292,-1133.5 3713,-1133.5 6310,-1133.5 6310,-523.5 -291.5,-523.5 -291.5,-1133.5 1284,-1133.5 ; 2173,-1133.5 2173,-523.5 ; 3440,-726.83 3440,-523.5 ; 4280,-726.83 4280,-523.5 ; 4902,-1140 4902,-937.17
  text "COMPONENTS MARKED 'DNP' SHOULD NOT BE POPULATED." at 1153.5,-318.5 h60
  text "ASSEMBLY VARIANT:" at 1153,-434 h60
  text ".VariantName" at 2189,-434 h60
  text "PCB VIEWED FROM TOP SIDE" at -228.5,-655.67 h60
  text "BOARD #:" at 2248,-655.67 h60
  text ".PRJ_Number" at 2793.5,-655.67 h60
  text "REV:" at 3638,-655.67 h60
  text ".PCB_Rev" at 3929.5,-655.67 h60
  text "SVN REV:" at 4476,-655.67 h60
  text ".VersionControl_RevNumber" at 4982,-655.67 h60
  text "IGNORE ->" at -228.5,-858.49 h60
  text "PLOT NAME =" at -228.5,-1064.34 h60
  text ".plot_File_Name" at 577,-1064.34 h60
  text "GENERATED    :" at 2250,-1064.34 h60
  text ".Print_Date" at 3119.5,-1064.34 h60
  text ".Print_Time" at 3848.5,-1064.34 h60
  text "TEXAS INSTRUMENTS" at 5113,-1064.34 h60
M6 Assembly Bottom:
  lines w10: -292.5,-727.33 6309.5,-727.33 ; -290.5,-930.67 6309.5,-930.67 ; 1115.5,-1140.5 1115.5,-937.67 ; 1737.5,-727.33 1737.5,-524 ; 2577.5,-727.33 2577.5,-524 ; 3844.5,-1134 3844.5,-524 ; 4733.5,-1134 6309,-1134 6309,-524 -292.5,-524 -292.5,-1134 2304.5,-1134 6309.5,-1134 6309.5,-524
  text "COMPONENTS MARKED 'DNP' SHOULD NOT BE POPULATED." at 6102,-318 h60
  text ".VariantName" at 5058,-434 h60
  text "ASSEMBLY VARIANT:" at 6097,-434 h60
  text ".VersionControl_RevNumber" at 1035.5,-656.17 h60
  text "SVN REV:" at 1541.5,-656.17 h60
  text ".PCB_Rev" at 2088,-656.17 h60
  text "REV:" at 2379.5,-656.17 h60
  text ".PRJ_Number" at 3224,-656.17 h60
  text "BOARD #:" at 3769.5,-656.17 h60
  text "PCB VIEWED FROM BOTTOM SIDE" at 6246,-656.17 h60
  text "IGNORE ->" at 2547.85,-858.49 h60
  text "TEXAS INSTRUMENTS" at 904.5,-1064.84 h60
  text ".Print_Time" at 2169,-1064.84 h60
  text ".Print_Date" at 2898,-1064.84 h60
  text "GENERATED    :" at 3767.5,-1064.84 h60
  text ".plot_File_Name" at 5440.5,-1064.84 h60
  text "PLOT NAME =" at 6246,-1064.84 h60
M9 Title Sheet:
  drawing of 57 lines, arcs and shapes, not listed
  text "1" at 739.84,8036.5 h70
  text "2" at 3235.5,8036.5 h70
  text "3" at 5724.84,8036.5 h70
  text "4" at 8231.51,8036.5 h70
  text "5" at 10730.5,8036.5 h70
  text "6" at 13235.5,8036.5 h70
  text "A" at -416.5,6893.5 h70
  text "A" at 14383.5,6893.5 h70
  text "B" at -416.5,4513.5 h70
  text "B" at 14383.5,4513.5 h70
  text "C" at -416.5,2138.5 h70
  text "C" at 14383.5,2138.5 h70
  text "PROJECT TITLE:" at 11343.5,277.5 h45
  text ".PRJ_Title" at 11393.5,144.17 h70
  text "DESIGNED FOR:" at 11343.5,-23.5 h45
  text ".PRJ_Customer" at 11393.5,-163.5 h70
  text "D" at -416.5,-231.5 h70
  text "D" at 14383.5,-231.5 h70
  text "FILE NAME:" at 11343.5,-323.5 h45
  text ".PCB_File_Name_No_Path" at 11393.5,-443.5 h70
  text "Texas Instruments (TI) and/or its licensors do not warrant the accuracy or completeness of this specification" at 6374,-605.34 h45
  text "ENGINEER:" at 11343.5,-613.5 h45
  text "LAYOUT BY:" at 12848.5,-613.5 h45
  text "or any information contained therein. TI and/or its licensors do not warrant that this design will meet" at 6329.01,-718 h45
  text ".PRJ_Engineer" at 11393.5,-768.49 h70
  text ".PCB_Layout" at 12899,-768.49 h70
  text "the specifications, will be suitable for your application or fit for any particular purpose, or will operate in" at 6329.01,-830.67 h45
  text ".Layer_Name" at 577,-858.49 h60
  text "ALTIUM DESIGNER VERSION:" at 12848.5,-923.5 h45
  text "an implementation. TI and/or its licensors do not warrant that the design is production worthy. You should" at 6329.01,-943.33 h45
  text "completely validate and test your design implementation to confirm the system functionality for your application." at 6374,-1056 h45
  text ".print_Scale" at 11393.5,-1056.83 h70
  text ".Application_BuildNumber" at 12899,-1056.83 h70
  text "1" at 739.84,-1263.5 h70
  text "2" at 3235.5,-1263.5 h70
  text "3" at 5724.84,-1263.5 h70
  text "4" at 8231.51,-1263.5 h70
  text "5" at 10730.5,-1263.5 h70
  text "6" at 13235.5,-1263.5 h70
M10 Fab Notes:
  drawing of 212 lines, arcs and shapes, not listed
  text "DESIGN INFORMATION" at 12381.02,6810 h60
  text "(REFER ALSO ARRAY/PANEL PROFILING INFORMATION)" at 12019.46,6648.29 h60
  text "BOARD SIZE" at 11333.46,6644 h60
  text "2100MIL" at 11795.78,6516.18 h60
  text "X" at 12301.46,6516.18 h60
  text "4200MIL" at 12532.78,6516.18 h60
  text "Number of Layers :" at 11736.46,6319 h60
  text "6" at 12831.27,6309 h60
  text "MIN. TRACK WIDTH:" at 11736.46,6180 h60
  text "10" at 12810,6180 h60
  text "MIL" at 12987.46,6180 h60
  text "5.9" at 12785,6050 h60
  text "MIN. CLEARANCE:" at 11736.46,6048 h60
  text "MIL" at 12987.46,6048 h60
  text "MIN. VIA PAD SIZE:" at 11736.46,5916 h60
  text "24" at 12802.71,5916 h60
  text "MIL" at 12987.46,5916 h60
  text "0.15mm (6MIL)" at 12431.46,5774.29 h60
  text "MINIMUM ANNULAR RING" at 11407.23,5770 h60
  text "EXTERNAL" at 13139.46,5770 h60
  text "PER" at 11607.23,5652 h60
  text "IPC-D-275 CLASS 2 LEVEL C" at 11827.23,5652 h60
  text "MIL, HOLES" at 13315.46,5539.71 h60
  text "+/-" at 12923,5539 h60
  text "+/-" at 13777,5539 h60
  text "REGISTRATION TOLERANCES:" at 11407.23,5534 h60
  text "METAL" at 12607,5534 h60
  text "5" at 13183.2,5534 h60
  text "3" at 14016.2,5534 h60
  text "MIL" at 14132.46,5534 h60
  text "MATERIAL:" at 11332.46,5324.54 h60
  text "FR-4 High Tg" at 12318.9,5184.21 h60
  text "FR-408" at 11753.46,5175.64 h60
  text "X" at 12165.46,5175.64 h60
  text "OTHER" at 13241.46,5175.64 h60
  text "62 MIL (1.6mm) +/-10%" at 12073.56,5012.92 h60
  text "THICKNESS:" at 11407.23,5008.64 h60
  text "X" at 11945.4,5008.64 h60
  text "OTHER" at 13358.46,5008.64 h60
  text "TOLERANCE:" at 11407.23,4850.64 h60
  text "X" at 12246.53,4850.64 h60
  text "ANSI IPC-6012 TYPE 3 CLASS 2" at 12433.48,4850.64 h60
  text "OTHER +/-" at 12433.46,4694.64 h60
  text "BOW & TWIST:" at 11407.23,4537.64 h60
  text "X" at 12246.53,4537.64 h60
  text "ANSI IPC-6012 TYPE 3 CLASS 2" at 12433.48,4537.64 h60
  text "OTHER +/-" at 12433.46,4379.13 h60
  text "COPPER THICKNESS (FINISHED):" at 11332.46,4243.64 h60
  text "0.7MIL (0.5oz)" at 12212.46,4090.92 h60
  text "2MIL (1.4oz)" at 12979.46,4090.92 h60
  text "2.8MIL (2oz)" at 13706.46,4090.92 h60
  text "SIGNAL:" at 11689.46,4086.64 h60
  text "X" at 12084,4086 h60
  text "1.4MIL (1oz)" at 12212.46,3933.92 h60
  text "2.8MIL (2oz)" at 12979.46,3933.92 h60
  text "N/A" at 13706,3934.29 h60
  text "PLANE:" at 11695,3930 h60
  text "X" at 12085.42,3929.64 h60
  text "DRILLING:" at 11332.46,3790.64 h60
  text "REFERENCE:" at 11407.23,3673.64 h60
  text "X" at 12055.46,3673.64 h60
  text "AS SHOWN" at 12242.46,3673.64 h60
  text "X" at 12956.46,3673.64 h60
  text "NC_DRILL FILES" at 13093.46,3673.64 h60
  text "PTH MIN COPPER THICKNESS:" at 11407.23,3515.64 h60
  text "X" at 12757.46,3515.64 h60
  text "1MIL" at 12894.46,3515.64 h60
  text "OTHER" at 13391.46,3515.64 h60
  text "BOARD FINISH:" at 11332.46,3356.64 h60
  text "SILKSCREEN:" at 11487.68,3238.64 h60
  text "X" at 12436.46,3238.64 h60
  text "TOP" at 12562.46,3238.64 h60
  text "X" at 12946.46,3238.64 h60
  text "BOTTOM" at 13073.46,3238.64 h60
  text "SILKSCREEN COLOR:" at 11487.68,3071.64 h60
  text "X" at 12435.42,3071.64 h60
  text "WHITE" at 12562.46,3071.64 h60
  text "OTHER" at 13073.46,3071.64 h60
  text "SOLDER RESIST COLOR:" at 11487.68,2901.64 h60
  text "X" at 12055.42,2742.44 h60
  text "GREEN" at 12182.46,2742.44 h60
  text "BLUE" at 12773.46,2742.44 h60
  text "OTHER" at 13311.46,2742.44 h60
  text "IMMERSION GOLD (ENIG)" at 12393.46,2553.92 h60
  text "ENEPIG" at 13731,2550.64 h60
  text "SURFACE FINISH:" at 11332.46,2549.64 h60
  text "IMM. TIN/SILVER OR EQUIV" at 11662,2392.64 h60
  text "OTHER" at 13093.46,2392.64 h60
  text "X" at 11495,2390 h60
  text "X" at 12200,2215 h60
  text "ARRAY/PANEL:" at 11332.46,2213.64 h60
  text "CUT AND TRIM PER MECH LAYER 1" at 12393.46,2209.35 h60
  text "N.C. ROUTE" at 12393.46,2057.64 h60
  text "V. SCORE" at 13259.46,2057.64 h60
  text "CERTIFICATION:" at 11332.46,1920.64 h60
  text "MATERIALS AND WORKMANSHIP FOR ALL PCBS" at 12057.46,1920.64 h60
  text "TO MEET OR EXCEED THE REQUIREMENTS OF:" at 12057.46,1822.64 h60
  text "X" at 11683.96,1686.13 h60
  text "ANSI IPC-A-600F CLASS ->" at 11822.96,1686.13 h60
  text "X" at 13462.02,1686.13 h60
  text "2" at 13580.96,1686.14 h60
  text "1" at 13265.96,1684.64 h60
  text "3" at 13934.96,1684.64 h60
  text "X" at 11686.02,1526.64 h60
  text "UL 94V-0" at 11822.96,1526.64 h60
  text "X" at 12498.02,1526.64 h60
  text "RoHS" at 12634.96,1526.64 h60
  text "OTHER" at 13279.36,1526.64 h60
  text "PER ORDER" at 13676.42,1526.64 h60
  text "ADDITIONAL REQUIREMENTS:" at 11332.46,1385.64 h60
  text "MICROSECTION:" at 11407.23,1270.64 h60
  text "YES" at 12312.96,1270.64 h60
  text "REQUIRED" at 13174.46,1114.49 h60
  text "BARE BOARD ELEC. TEST:" at 11407.23,1111.64 h60
  text "NONE" at 12712.96,1111.64 h60
  text "PER ORDER" at 13766.46,1111.64 h60
  text "X" at 13050,1110 h60
  text "MANUFACTURER'S UL:" at 11407.23,954.64 h60
  text "RAIL" at 12572.96,950.35 h60
  text "METAL" at 13064.77,950.35 h60
  text "X" at 13440,950 h60
  text "SILK" at 13576.46,950.35 h60
  text ".Layer_Name" at 577,-858.49 h60
M11 Gerber Information:
  lines w10: -292,-930.17 6308,-930.17 ; -292,-726.83 6310,-726.83 ; -292,-523.5 -292,-1133.5 3713,-1133.5 6310,-1133.5 6310,-523.5 -291.5,-523.5 -291.5,-1133.5 1284,-1133.5 ; 2173,-1133.5 2173,-523.5 ; 3440,-726.83 3440,-523.5 ; 4280,-726.83 4280,-523.5 ; 4902,-1140 4902,-937.17
  text "ALL ARTWORK VIEWED FROM TOP SIDE" at -228.5,-655.67 h60
  text "BOARD #:" at 2248,-655.67 h60
  text ".PRJ_Number" at 2793.5,-655.67 h60
  text "REV:" at 3638,-655.67 h60
  text ".PCB_Rev" at 3929.5,-655.67 h60
  text "SVN REV:" at 4476,-655.67 h60
  text ".VersionControl_RevNumber" at 4982,-655.67 h60
  text "LAYER NAME =" at -228.5,-858.49 h60
  text "PLOT NAME =" at -228.5,-1064.34 h60
  text ".plot_File_Name" at 577,-1064.34 h60
  text "GENERATED    :" at 2250,-1064.34 h60
  text ".Print_Date" at 3119.5,-1064.34 h60
  text ".Print_Time" at 3848.5,-1064.34 h60
  text "TEXAS INSTRUMENTS" at 5113,-1064.34 h60
M12 Stackup:
  lines w9: 7210,6557.5 10945,6557.5 ; 7210,6726.4 10945,6726.4 ; 7150,5180 ccw(c7205,5180) 7205,5125 10950,5125 ccw(c10950,5180) 11005,5180 11005,6855 ccw(c10950,6855) 10950,6910 7205,6910 ccw(c7205,6855) 7150,6855 7150,5180
  text "Layer Stack Up Detail for: PMP9372_REVA.PcbDoc" at 7210,6766.7 h70
  text "Layer" at 7210,6663.4 h39
  text "Gerber" at 8527.7,6663.4 h39
  text "Copper" at 9312.57,6663.4 h39
  text "Dielectric" at 10161.12,6663.4 h39
  text "Name" at 7210,6585.4 h39
  text "Document" at 8527.7,6585.4 h39
  text "Thickness" at 9312.57,6585.4 h39
  text "Material" at 10161.12,6585.4 h39
  text "Top Solder Mask" at 7210,6474.91 h55
  text "(.GTS)" at 8527.7,6474.91 h55
  text "Solder Resist" at 10161.12,6474.91 h55
  text "Top Layer" at 7210,6318.72 h55
  text "(.GTL)" at 8527.7,6318.72 h55
  text "0.7mil" at 9312.57,6318.72 h55
  text "FR-4" at 10161.12,6240.63 h55
  text "InternalPlane1" at 7210,6162.53 h55
  text "(.GP1)" at 8527.7,6162.53 h55
  text "1.4mil" at 9312.57,6162.53 h55
  text "FR-4" at 10161.12,6084.44 h55
  text "MidLayer2" at 7210,6006.34 h55
  text "(.G1)" at 8527.7,6006.34 h55
  text "0.7mil" at 9312.57,6006.34 h55
  text "FR-4" at 10161.12,5928.25 h55
  text "MidLayer3" at 7210,5850.16 h55
  text "(.G2)" at 8527.7,5850.16 h55
  text "0.7mil" at 9312.57,5850.16 h55
  text "FR-4" at 10161.12,5772.06 h55
  text "InternalPlane2" at 7210,5693.97 h55
  text "(.GP2)" at 8527.7,5693.97 h55
  text "1.4mil" at 9312.57,5693.97 h55
  text "FR-4" at 10161.12,5615.88 h55
  text "Bottom Layer" at 7210,5537.78 h55
  text "(.GBL)" at 8527.7,5537.78 h55
  text "0.7mil" at 9312.57,5537.78 h55
  text "Bottom Solder Mask" at 7210,5381.59 h55
  text "(.GBS)" at 8527.7,5381.59 h55
  text "Solder Resist" at 10161.12,5381.59 h55
  text ".Layer_Name" at 577,-858.49 h60
M13 Component Bodies Top:
  text ".Layer_Name" at 577,-858.49 h60
M14 Component Bodies Bottom:
  text ".Layer_Name" at 577,-858.49 h60
M15 Courtyards Top:
  text ".Layer_Name" at 577,-858.49 h60
M16 Courtyards Bottom:
  text ".Layer_Name" at 577,-858.49 h60
Drill Drawing:
  text ".legend" at 5122.5,725.5 h60
  text "Drill Table" at 5147.5,540.5 h60
  text ".Layer_Name" at 577,-858.49 h60

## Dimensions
0,0 to 0,2100 on M2 Board Dimensions
0,0 to 4200,0 on M2 Board Dimensions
